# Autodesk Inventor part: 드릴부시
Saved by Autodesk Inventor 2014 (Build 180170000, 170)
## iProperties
Created: 2025-02
Part Number: 드릴부시
Material: 일반
Document SubType Name: Modeling
Designer: dg
Density: 1 g/cm^3
Appearance: 기본값
Author: dg
Author: jhkim
Creation Date: 2025-02-05
Sending System: Autodesk Inventor 2025
Preprocessor: ST-DEVELOPER v20
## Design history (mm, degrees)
node "드릴부시1"
node "솔리드1"
node "기준1"
